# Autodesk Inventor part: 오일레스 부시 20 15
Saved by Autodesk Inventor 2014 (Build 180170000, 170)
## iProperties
Created: 2024-08
Part Number: 오일레스 부시 20 15
Material: 일반
Document SubType Name: Modeling
Designer: dg
Density: 1 g/cm^3
Appearance: 기본값
Author: dg
Author: jhkim
Creation Date: 2024-08-09
Sending System: Autodesk Inventor 2025
Preprocessor: ST-DEVELOPER v20
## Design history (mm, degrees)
node "오일레스 부시 20 151"
node "솔리드1"
node "기준1"
